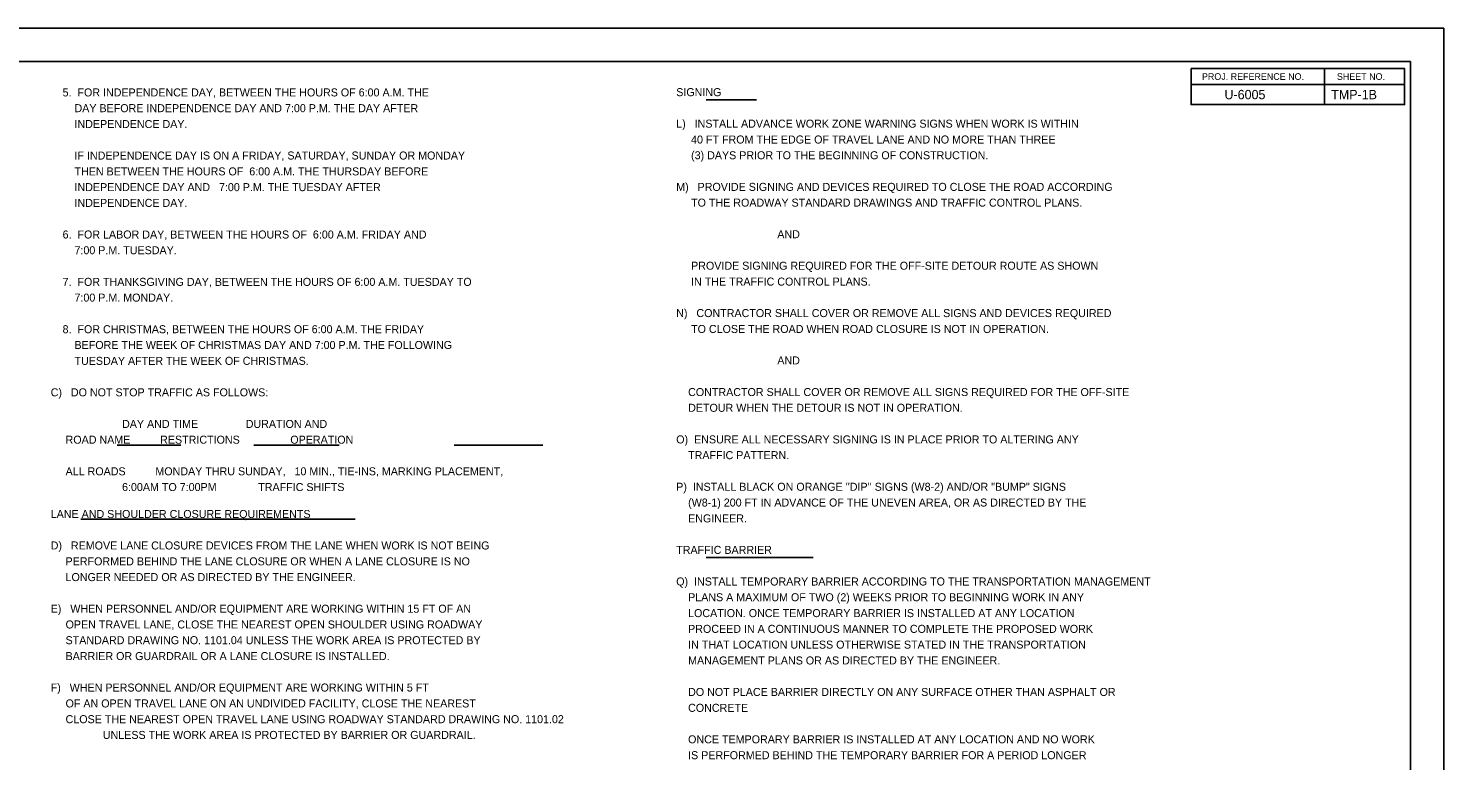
# Model space of a CAD drawing. Extents: x 762655 to 770567, y 650864 to 655190.
# Drawn here: x 763282 to 764343, y 653330 to 653879 of the extents above; entities that cross this region are included whole.
import ezdxf

# ---------------------------------------------------------------- set-up
doc = ezdxf.new("R2010")
doc.units = 0
for name, color, linetype in [('Default', 7, 'Continuous'), ('DEV TRANSPORTATION OPERATIONS PLAN SHEET', 7, 'Continuous'), ('Sheet Plot Border Outside CELL', 7, 'Continuous')]:
    doc.layers.add(name, color=color, linetype=linetype)

msp = doc.modelspace()

# ---------------------------------------------------------------- linework, layer by layer
at = {"layer": 'Default'}
for p, q in [((763789.8, 653825.2), (763827.5, 653825.2)), ((763348.3, 653566.3), (763396, 653566.3)), ((763450.7, 653566.3), (763514.8, 653566.3)), ((763600.8, 653566.3), (763667.5, 653566.3)), ((763321, 653510.7), (763526.8, 653510.7)), ((763789.8, 653482.1), (763870.1, 653482.1))]:
    msp.add_line(p, q, dxfattribs=at)
at = {"layer": 'DEV TRANSPORTATION OPERATIONS PLAN SHEET'}
msp.add_line((764253.5, 653836.6), (764313.5, 653836.6), dxfattribs=at)
for points in [[(764317.9, 653853.8), (762817.8, 653853.8), (762817.8, 652803.8), (764317.9, 652803.8)], [(764153.5, 653848.6), (764253.5, 653848.6), (764253.5, 653836.6), (764153.5, 653836.6)], [(764253.5, 653836.6), (764313.5, 653836.6), (764313.5, 653848.6), (764253.5, 653848.6)], [(764253.5, 653836.6), (764153.5, 653836.6), (764153.5, 653821.6), (764253.5, 653821.6)], [(764253.5, 653836.6), (764313.5, 653836.6), (764313.5, 653821.6), (764253.5, 653821.6)]]:
    msp.add_lwpolyline(points, close=True, dxfattribs=at)
at = {"layer": 'Sheet Plot Border Outside CELL'}
msp.add_lwpolyline([(762654.9, 652778.8), (764342.9, 652778.8), (764342.9, 653878.8), (762654.9, 653878.8)], close=True, dxfattribs=at)

# ---------------------------------------------------------------- texts
at = {"layer": 'Default'}
for s, p in [('           5.  FOR INDEPENDENCE DAY, BETWEEN THE HOURS OF 6:00 A.M. THE', (763282.8, 653827.7)), ('       SIGNING', (763751.8, 653827.9)), ('               DAY BEFORE INDEPENDENCE DAY AND 7:00 P.M. THE DAY AFTER', (763282.8, 653815.9)), ('               INDEPENDENCE DAY.', (763282.8, 653804)), ('       L)   INSTALL ADVANCE WORK ZONE WARNING SIGNS WHEN WORK IS WITHIN ', (763751.8, 653804.3)), ('            40 FT FROM THE EDGE OF TRAVEL LANE AND NO MORE THAN THREE', (763751.8, 653792.4)), ('               IF INDEPENDENCE DAY IS ON A FRIDAY, SATURDAY, SUNDAY OR MONDAY  ', (763282.8, 653780.4)), ('            (3) DAYS PRIOR TO THE BEGINNING OF CONSTRUCTION.', (763751.8, 653780.6)), ('               THEN BETWEEN THE HOURS OF  6:00 A.M. THE THURSDAY BEFORE ', (763282.8, 653768.5)), ('               INDEPENDENCE DAY AND   7:00 P.M. THE TUESDAY AFTER', (763282.8, 653756.7)), ('       M)   PROVIDE SIGNING AND DEVICES REQUIRED TO CLOSE THE ROAD ACCORDING', (763751.8, 653756.9)), ('               INDEPENDENCE DAY.   ', (763282.8, 653744.9)), ('            TO THE ROADWAY STANDARD DRAWINGS AND TRAFFIC CONTROL PLANS.', (763751.8, 653745.1)), ('           6.  FOR LABOR DAY, BETWEEN THE HOURS OF  6:00 A.M. FRIDAY AND', (763282.8, 653721.2)), ('                                         AND', (763751.8, 653721.4)), ('               7:00 P.M. TUESDAY.', (763282.8, 653709.4)), ('            PROVIDE SIGNING REQUIRED FOR THE OFF-SITE DETOUR ROUTE AS SHOWN', (763751.8, 653697.8)), ('           7.  FOR THANKSGIVING DAY, BETWEEN THE HOURS OF 6:00 A.M. TUESDAY TO', (763282.8, 653685.7)), ('            IN THE TRAFFIC CONTROL PLANS.', (763751.8, 653685.9)), ('               7:00 P.M. MONDAY.', (763282.8, 653673.9)), ('       N)   CONTRACTOR SHALL COVER OR REMOVE ALL SIGNS AND DEVICES REQUIRED ', (763751.8, 653662.3)), ('           8.  FOR CHRISTMAS, BETWEEN THE HOURS OF 6:00 A.M. THE FRIDAY', (763282.8, 653650.2)), ('            TO CLOSE THE ROAD WHEN ROAD CLOSURE IS NOT IN OPERATION.', (763751.8, 653650.4)), ('               BEFORE THE WEEK OF CHRISTMAS DAY AND 7:00 P.M. THE FOLLOWING', (763282.8, 653638.4)), ('               TUESDAY AFTER THE WEEK OF CHRISTMAS.', (763282.8, 653626.5)), ('                                         AND', (763751.8, 653626.8)), ('       C)   DO NOT STOP TRAFFIC AS FOLLOWS:  ', (763282.8, 653602.9)), ('           CONTRACTOR SHALL COVER OR REMOVE ALL SIGNS REQUIRED FOR THE OFF-SITE ', (763751.8, 653603.1)), ('           DETOUR WHEN THE DETOUR IS NOT IN OPERATION.', (763751.8, 653591.3)), ('                               DAY AND TIME                DURATION AND', (763282.8, 653579.2)), ('            ROAD NAME          RESTRICTIONS                 OPERATION', (763282.8, 653567.4)), ('       O)  ENSURE ALL NECESSARY SIGNING IS IN PLACE PRIOR TO ALTERING ANY', (763751.8, 653567.6)), ('           TRAFFIC PATTERN.', (763751.8, 653555.8)), ('            ALL ROADS          MONDAY THRU SUNDAY,   10 MIN., TIE-INS, MARKING PLACEMENT,', (763282.8, 653543.7)), ('                               6:00AM TO 7:00PM              TRAFFIC SHIFTS', (763282.8, 653531.9)), ('       P)  INSTALL BLACK ON ORANGE \'\'DIP\'\' SIGNS (W8-2) AND/OR "BUMP" SIGNS  ', (763751.8, 653532.1)), ('           (W8-1) 200 FT IN ADVANCE OF THE UNEVEN AREA, OR AS DIRECTED BY THE ', (763751.8, 653520.3)), ('       LANE AND SHOULDER CLOSURE REQUIREMENTS', (763282.8, 653511.7)), ('           ENGINEER. ', (763751.8, 653508.4)), ('       D)   REMOVE LANE CLOSURE DEVICES FROM THE LANE WHEN WORK IS NOT BEING', (763282.8, 653488.1)), ('       TRAFFIC BARRIER', (763751.8, 653484.8)), ('            PERFORMED BEHIND THE LANE CLOSURE OR WHEN A LANE CLOSURE IS NO ', (763282.8, 653476.2)), ('            LONGER NEEDED OR AS DIRECTED BY THE ENGINEER.', (763282.8, 653464.4)), ('       Q)  INSTALL TEMPORARY BARRIER ACCORDING TO THE TRANSPORTATION MANAGEMENT', (763751.8, 653461.1)), ('       E)   WHEN PERSONNEL AND/OR EQUIPMENT ARE WORKING WITHIN 15 FT OF AN', (763282.8, 653440.7)), ('           PLANS A MAXIMUM OF TWO (2) WEEKS PRIOR TO BEGINNING WORK IN ANY', (763751.8, 653449.3)), ('           LOCATION. ONCE TEMPORARY BARRIER IS INSTALLED AT ANY LOCATION', (763751.8, 653437.4)), ('            OPEN TRAVEL LANE, CLOSE THE NEAREST OPEN SHOULDER USING ROADWAY ', (763282.8, 653428.9)), ('           PROCEED IN A CONTINUOUS MANNER TO COMPLETE THE PROPOSED WORK', (763751.8, 653425.6)), ('            STANDARD DRAWING NO. 1101.04 UNLESS THE WORK AREA IS PROTECTED BY ', (763282.8, 653417.1)), ('           IN THAT LOCATION UNLESS OTHERWISE STATED IN THE TRANSPORTATION', (763751.8, 653413.8)), ('            BARRIER OR GUARDRAIL OR A LANE CLOSURE IS INSTALLED.', (763282.8, 653405.2)), ('           MANAGEMENT PLANS OR AS DIRECTED BY THE ENGINEER.', (763751.8, 653401.9)), ('       F)   WHEN PERSONNEL AND/OR EQUIPMENT ARE WORKING WITHIN 5 FT', (763282.8, 653381.6)), ('           DO NOT PLACE BARRIER DIRECTLY ON ANY SURFACE OTHER THAN ASPHALT OR', (763751.8, 653378.3)), ('            OF AN OPEN TRAVEL LANE ON AN UNDIVIDED FACILITY, CLOSE THE NEAREST', (763282.8, 653369.7)), ('           CONCRETE', (763751.8, 653366.4)), ('            CLOSE THE NEAREST OPEN TRAVEL LANE USING ROADWAY STANDARD DRAWING NO. 1101.02', (763282.8, 653357.9)), ('   UNLESS THE WORK AREA IS PROTECTED BY BARRIER OR GUARDRAIL.', (763330.8, 653346.1)), ('           ONCE TEMPORARY BARRIER IS INSTALLED AT ANY LOCATION AND NO WORK', (763751.8, 653342.8)), ('           IS PERFORMED BEHIND THE TEMPORARY BARRIER FOR A PERIOD LONGER', (763751.8, 653330.9))]:
    msp.add_text(s, height=6, dxfattribs=at).set_placement(p)
at = {"layer": 'DEV TRANSPORTATION OPERATIONS PLAN SHEET'}
for s, height, p in [('PROJ. REFERENCE NO.', 4.999, (764161.6, 653840.1)), ('SHEET NO.', 5, (764262.8, 653840.1))]:
    msp.add_text(s, height=height, rotation=0.0006, dxfattribs=at).set_placement(p)
for s, p in [('U-6005', (764178.5, 653825.6)), ('TMP-1B  ', (764258.5, 653825.6))]:
    msp.add_text(s, height=7, dxfattribs=at).set_placement(p)

doc.saveas('drawing.dxf')
